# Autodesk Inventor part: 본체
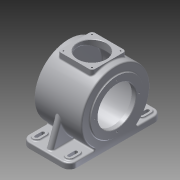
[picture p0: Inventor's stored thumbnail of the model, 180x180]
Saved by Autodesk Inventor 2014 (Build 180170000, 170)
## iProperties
Created: 2015-06
Part Number: 본체
Material: 알루미늄 6061
Document SubType Name: Modeling
Designer: SEC
Density: 2.71 g/cm^3
Appearance: 알루미늄 - 평지
Author: SEC
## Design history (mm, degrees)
sketch "스케치1"
  geometry: C1 r 85 at (0, 0); 1 further point
  constraints: 1 centre point, 1 coincident
  dimensions: "d0" = 170 diameter of C1
extrude "돌출1" new body sketch "스케치1" stored distance "d1" = 118; taper "d2" = 0 deg
node "작업 평면1"
sketch "스케치2"
  geometry: L1 (-59, 115)-(59, 115); L2 (59, 115)-(59, -115); L3 (59, -115)-(-59, -115); L4 (-59, -115)-(-59, 115); L5 (-59, 115)-(59, -115); 2 further points
  constraints: 10 end point, 2 parallel, 1 coincident, 1 horizontal, 1 midpoint, 1 perpendicular
  dimensions: "d4" = 118 distance of L1.start L1.end; "d5" = 230 distance of L1.end L2.end
extrude "돌출2" join sketch "스케치2" distance "d6" = 14; taper "d7" = 0 deg
fillet "모깎기1" dims "d8" = 18
sketch "스케치3"
  geometry: C1 r 65 at (0, 0); A1 r 85 centre (0, 0) between (-71, -46.733) and (-71, 46.733) reference
  constraints: 1 centre point, 1 coincident
  dimensions: "d9" = 130 diameter of C1
extrude "돌출3" join sketch "스케치3" distance "d10" = 13; taper "d11" = 0 deg
node "작업 평면2"
sketch "스케치4"
  geometry: L1 (-42.5, 42.5)-(42.5, 42.5); L2 (42.5, 42.5)-(42.5, -42.5); L3 (42.5, -42.5)-(-42.5, -42.5); L4 (-42.5, -42.5)-(-42.5, 42.5); L5 (-42.5, 42.5)-(42.5, -42.5); 2 further points
  constraints: 10 end point, 2 parallel, 2 perpendicular, 1 coincident, 1 horizontal, 1 midpoint
  dimensions: "d13" = 85 distance of L1.end L2.end
extrude "돌출4" join sketch "스케치4" stored distance "d14" = 13; taper "d15" = 0 deg
sketch "스케치5"
  geometry: L1 (-115, -85)-(-115, -71) reference; L2 (-97, -71)-(-46.733, -71) reference; L3 (-112, -71)-(-97, -71) reference; L4 (-109, -71)-(-84.87, -4.703); A1 r 85 centre (0, 0) between (46.733, -71) and (-46.733, -71) reference; A2 r 3 centre (-112, -74) between (-112, -71) and (-115, -74) reference; 3 further points
  constraints: 2 end point, 1 point on circle, 1 point on line
  dimensions: "d17" = 6 distance from line of L4.start L1; "d18" = 110 deg angle of L3 L4
feature "리브1" sketch "스케치5" dims "d19" = 12, "d20" = 15, "d21" = 0, "d22" = 0, "d23" = 1, "d24" = 1
sketch "스케치6"
  geometry: L1 (7.5, -109)-(-7.5, -109) reference; L2 (-50, -81)-(-50, -97); L3 (-32, -81)-(-32, -97); A1 r 9 centre (-41, -97) between (-50, -97) and (-32, -97); A2 r 9 centre (-41, -81) between (-32, -81) and (-50, -81); 1 further point
  constraints: 4 end point, 4 point on circle, 4 tangent, 2 centre point, 1 parallel, 1 perpendicular
  dimensions: "d25" = 18 distance between parallel lines of L3 L2; "d26" = 16 distance of A1.centre A2.centre; "d27" = 97 vertical distance of A1.centre point (0, 0); "d28" = 41 horizontal distance of point (0, 0) A1.centre
extrude "돌출5" join sketch "스케치6" distance "d29" = 3; taper "d30" = 0 deg
fillet "모깎기3" dims "d31" = 3
sketch "스케치7"
  geometry: C1 r 65 at (0, 0); A1 r 85 centre (0, 0) between (71, 46.733) and (71, -46.733) reference; 2 further points
  constraints: 1 centre point, 1 coincident
  dimensions: "d41" = 130 diameter of C1
extrude "돌출6" join sketch "스케치7" distance "d42" = 3; taper "d43" = 0 deg
hole "구멍1" diameter "d34" = 95; stored, may be unused: countersink angle "d38" = 90 deg, drill point angle "d40" = 0 deg; dims "d35" = 6, "d36" = 4, "d37" = 2, "d39" = 11, "d44" = 10, "d45" = 10
hole "구멍2" diameter "d48" = 154; stored, may be unused: countersink angle "d52" = 90 deg, drill point angle "d54" = 0 deg; dims "d46" = 10, "d47" = 10, "d49" = 6, "d50" = 4, "d51" = 2, "d53" = 102
sketch "스케치8"
  geometry: L1 (51, 77)-(51, -77) reference; L2 (0, 0)-(51, 0); L3 (51, 31)-(47.5, 29.368); L4 (47.5, 29.368)-(47.5, 0)
  constraints: 6 end point, 2 point on line, 1 midpoint, 1 perpendicular
  dimensions: "d55" = 115 deg angle of L3 L1; "d56" = 3.5 distance between parallel lines of L1 L4; "d57" = 62 diameter of L3.start L2
revolve "회전1" sketch "스케치8" stored, may be unused: angle "d58" = 90 deg
hole "구멍3" diameter "d61" = 30; stored, may be unused: countersink angle "d65" = 90 deg, drill point angle "d67" = 0 deg; dims "d62" = 6, "d63" = 47, "d64" = 14, "d66" = 17, "d68" = 10, "d69" = 10
sketch "스케치9"
  geometry: 1 further point
hole "구멍4" sketch "스케치9" at (0, 0) diameter "d70" = 70; stored, may be unused: countersink angle "d74" = 90 deg, drill point angle "d76" = 0 deg; dims "d71" = 6, "d72" = 47, "d73" = 14, "d75" = 50
sketch "스케치10"
  geometry: C1 r 47.5 at (0, 0) reference; 1 further point
  dimensions: "d77" = 55 distance of C1.centre point (-55, 0)
hole "구멍5" sketch "스케치10" at (-55, 0) diameter "d78" = 3.242; stored, may be unused: countersink angle "d82" = 90 deg, drill point angle "d84" = 118 deg; dims "d79" = 15, "d80" = 47, "d81" = 14, "d83" = 17
sketch "스케치11"
  geometry: L1 (-35.5, 35.5)-(35.5, 35.5); L2 (35.5, 35.5)-(35.5, -35.5); L3 (35.5, -35.5)-(-35.5, -35.5); L4 (-35.5, -35.5)-(-35.5, 35.5); L5 (-35.5, 35.5)-(35.5, -35.5); C1 r 35 at (0, 0) reference; 1 further point
  constraints: 10 end point, 2 parallel, 2 perpendicular, 1 coincident, 1 horizontal, 1 midpoint
  dimensions: "d88" = 71 distance of L1.end L2.end
hole "구멍6" sketch "스케치11" at (-35.5, 35.5), (35.5, 35.5), (35.5, -35.5), (-35.5, -35.5) diameter "d89" = 3.242; stored, may be unused: countersink angle "d93" = 90 deg, drill point angle "d95" = 118 deg; dims "d90" = 10, "d91" = 47, "d92" = 14, "d94" = 13
fillet "모깎기4" dims "d96" = 7
sketch "스케치12"
  geometry: L1 (-9, 0)-(-9, 16) reference; L2 (9, 16)-(9, 0) reference; L3 (-4, 0)-(-4, 16); L4 (4, 16)-(4, 0); A1 r 9 centre (0, 0) between (-9, 0) and (9, 0) reference; A2 r 9 centre (0, 16) between (9, 16) and (-9, 16) reference; A3 r 4 centre (0, 0) between (-4, 0) and (4, 0); A4 r 4 centre (0, 16) between (4, 16) and (-4, 16); 1 further point
  constraints: 4 end point, 4 point on circle, 2 centre point, 3 other
  dimensions: "d97" = 8 distance between parallel lines of L4 L3
extrude "돌출7" cut sketch "스케치12" stored distance "d98" = 3; taper "d99" = 0 deg
fillet "모깎기5" dims "d100" = 0.3
chamfer "모따기1" distance "d101" = 1; stored, may be unused: second distance "d102" = 2, angle "d103" = 45 deg
fillet "모깎기6" dims "d104" = 7.5
fillet "모깎기7" dims "d105" = 3
fillet "모깎기9" dims "d107" = 3
fillet "모깎기10" dims "d108" = 3
fillet "모깎기12" dims "d110" = 3
node "작업 평면9"
  node "작업 평면8"
sketch "스케치13"
  geometry: 2 further points
  constraints: 1 coincident, 1 other
feature "엠보싱1" sketch "스케치13" dims "d0" = 170, "d114" = 0.5, "d115" = 0
fillet "모깎기13" dims "d116" = 3
node "솔리드1"
mirror "대칭1"
mirror "대칭2"
mirror "대칭3"
pattern_circular "원형 패턴1" dims angle "d86" = 360 deg
mirror "대칭4"
mirror "대칭5"
other parameters: "d3" = -85, "d12" = -173, "d113" = 65 deg
